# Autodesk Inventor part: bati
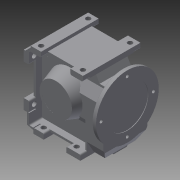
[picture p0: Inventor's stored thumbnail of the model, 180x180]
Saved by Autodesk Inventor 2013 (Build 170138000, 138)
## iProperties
Created: 2012-12
Part Number: bati
Material: Générique
Document SubType Name: Modeling
Designer: jost thierry
Density: 1 g/cm^3
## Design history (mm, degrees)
node "bati1"
node "bati"
node "bati_1"
node "Base1"
node "Base2"
